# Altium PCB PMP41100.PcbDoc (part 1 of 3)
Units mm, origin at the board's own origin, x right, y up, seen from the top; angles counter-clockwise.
Board outline 49.66 x 37.36 mm, 2 copper layers (Top Layer, Bottom Layer), stack 1.016 mm thick; 100 components, 64 nets, 348 pads, 1132 vias.
Unrouted connection lines stored in the file: 60.
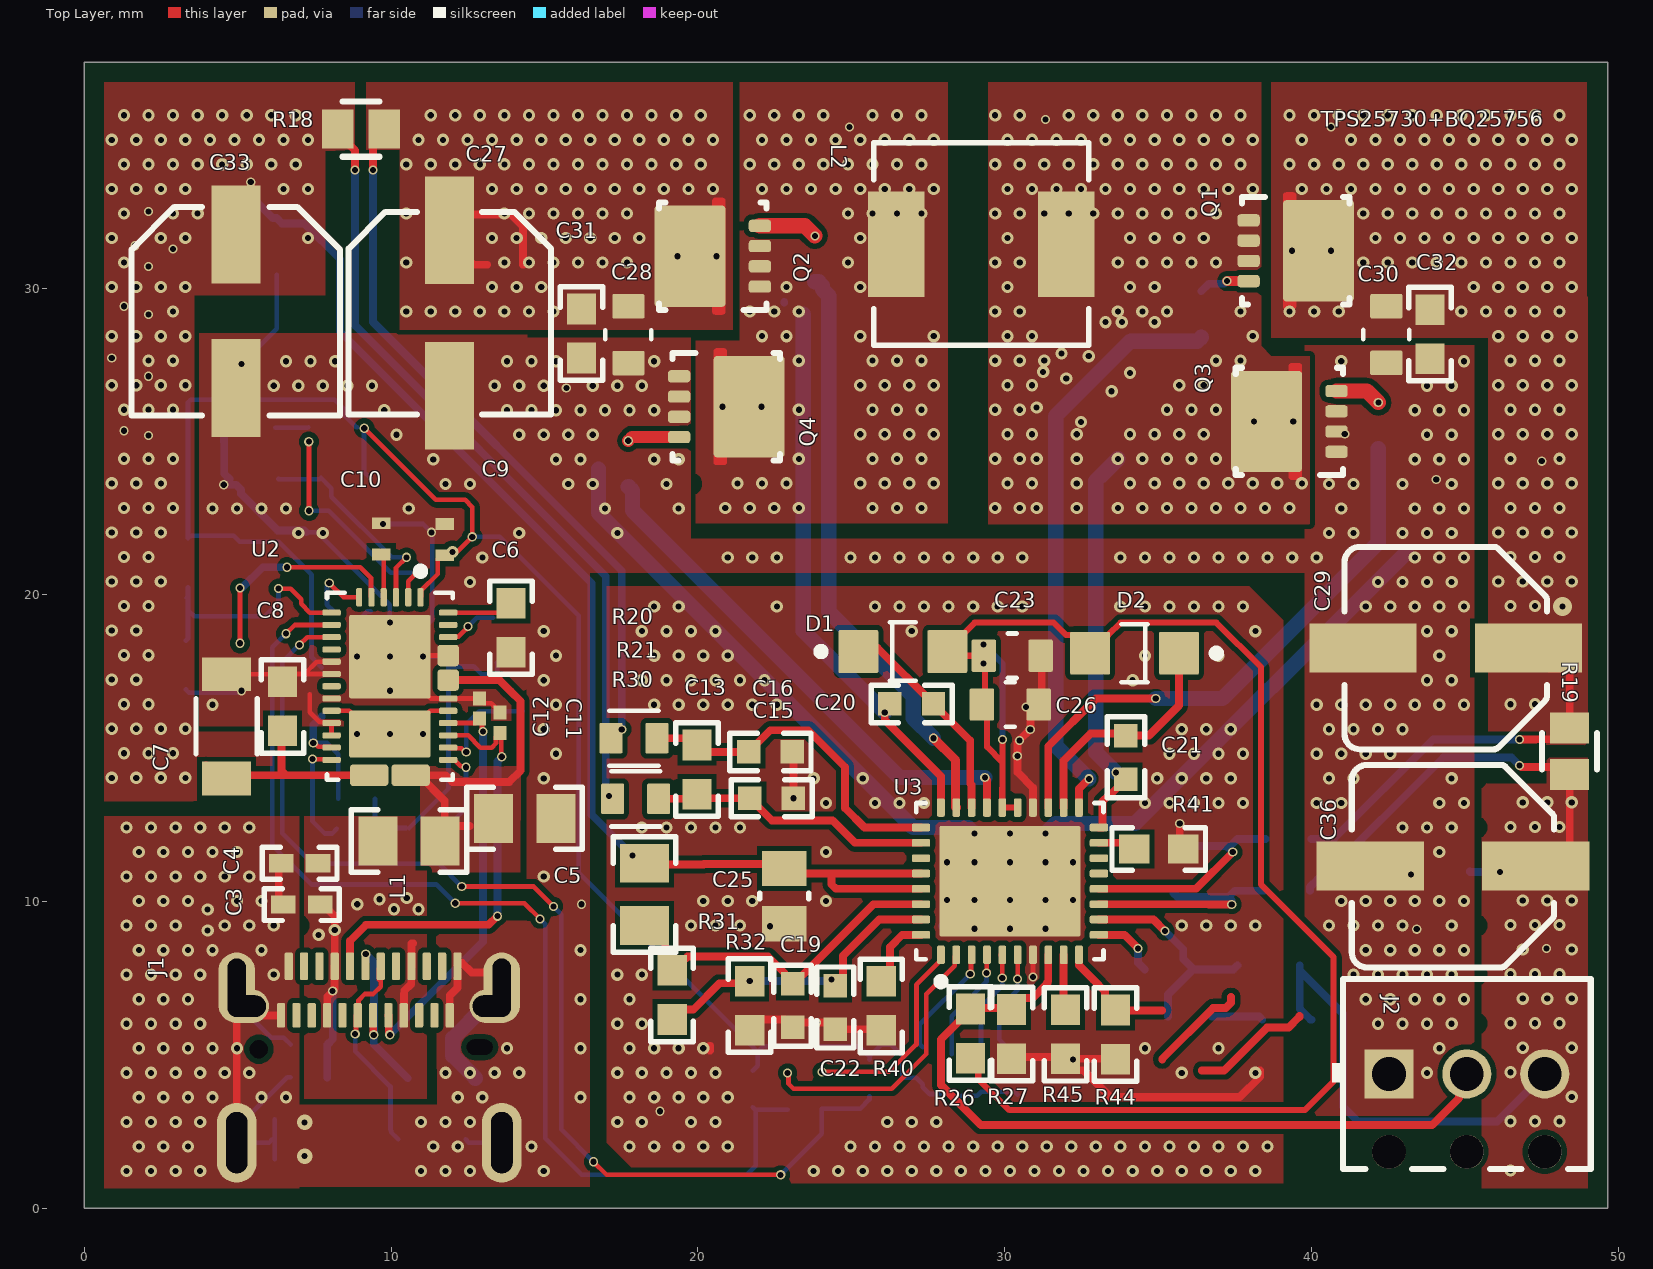
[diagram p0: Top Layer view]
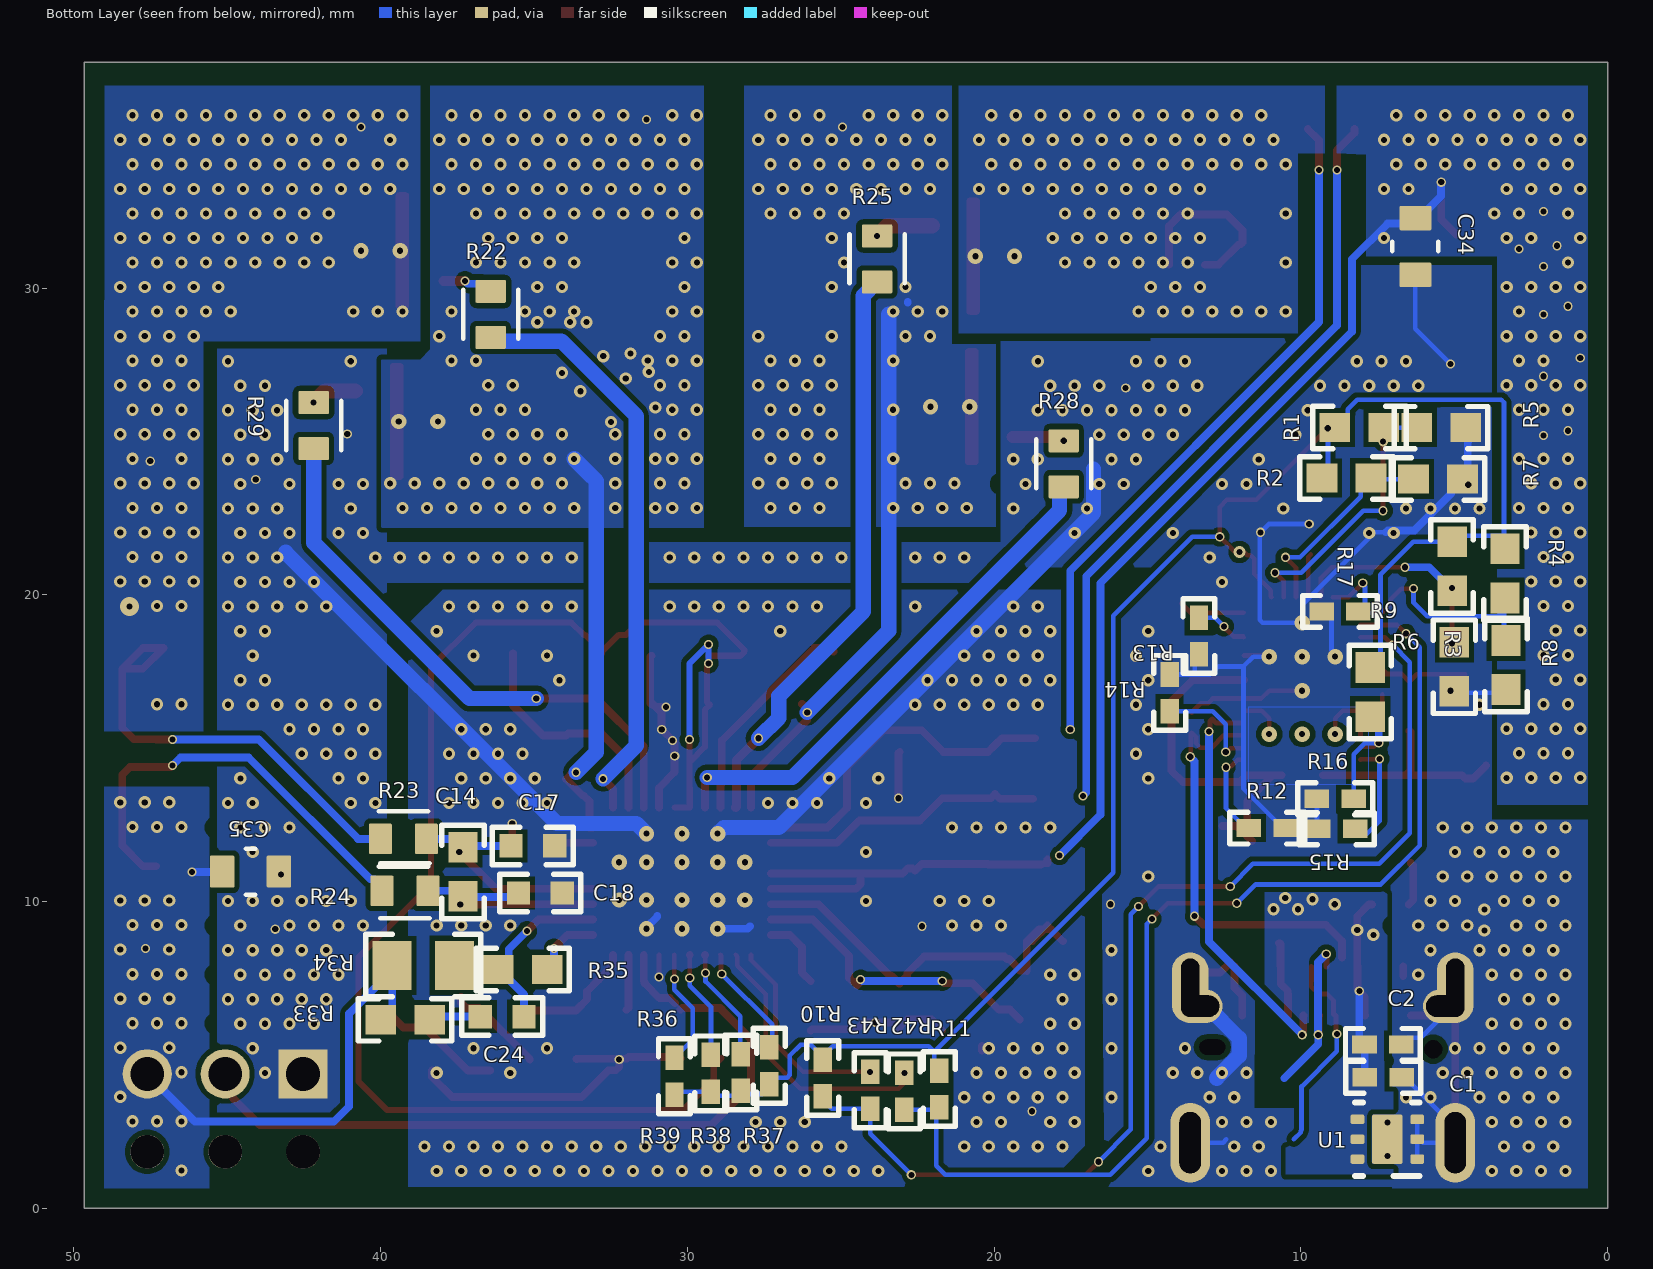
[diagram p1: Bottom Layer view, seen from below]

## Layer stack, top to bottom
Top Solder: solder mask 0.0102, Solder Resist, Dk 3.5
Top Layer: signal copper 0.0356
Dielectric1: core 0.9449, FR-4 High Tg, Dk 4.8
Bottom Layer: signal copper 0.0356
Bottom Solder: solder mask 0.0102, Solder Resist, Dk 3.5

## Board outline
0,0 0,37.358 49.657,37.358 49.657,0

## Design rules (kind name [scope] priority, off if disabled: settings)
AcuteAngle [All] p1: minimum=4.50000000000000E+0001 checktracksonly=FALSE
AssemblyTestPointUsage [All] p1: valid=2
BoardOutlineClearance BoardOutlineClearance_MountingHoles [OnCopper and InComponentClass('Mounting Holes')] p1: gap=1 ignorepadtopadclearanceinfootprint=FALSE
BoardOutlineClearance BoardOutlineClearance_Poly [OnCopper and IsPoly] p2: gap=0.635 ignorepadtopadclearanceinfootprint=FALSE
BoardOutlineClearance [OnCopper and Not InComponentClass('Logo') and not InComponentClass('FiducialMark') and not InRegion(1000,500,4000,800) and not InPoly] p3: gap=1.016 ignorepadtopadclearanceinfootprint=FALSE
Clearance "HV LV" [InNetClass('HV') vs InNetClass('LV')] p1: gap=0.17 ignorepadtopadclearanceinfootprint=TRUE
Clearance Clearance_Poly [InPolygon] p2: gap=0.17 ignorepadtopadclearanceinfootprint=TRUE
Clearance [All] p3: gap=0.17 ignorepadtopadclearanceinfootprint=TRUE
ComponentClearance ComponentClearance_MountingHoles_FiducialMarks [InComponentClass('Mounting Holes') vs InComponentClass('FiducialMark')] p1: gap=1.27 collisioncheckmode=3 verticalgap=0.254 showdistances=FALSE
ComponentClearance ComponentClearance_Shunt [InComponentClass('Header') vs InComponentClass('Shunt')] p2: gap=0.15 collisioncheckmode=3 verticalgap=0.15 showdistances=FALSE
ComponentClearance ComponentClearance_Logo [InComponentClass('Logo')] p3: gap=0.254 collisioncheckmode=3 verticalgap=0.254 showdistances=FALSE
ComponentClearance ComponentClearance_ScrewToNut [(HasFootprint('NY PMS 440 0025 PH')) vs (HasFootprint('Keystone_1902C'))] p4: gap=0.127 collisioncheckmode=3 verticalgap=0.254 showdistances=FALSE
ComponentClearance ComponentClearance_MountingHoles [InComponentClass('Mounting Holes')] p5: gap=0.254 collisioncheckmode=3 verticalgap=2540 showdistances=FALSE
ComponentClearance ComponentClearance_SmallPassives [HasFootprint('0201*') or HasFootprint('0402*') or HasFootprint('0508') or HasFootprint('0603*') or HasFootprint('0612') or HasFootprint('0805*') or HasFootprint('0815*') or HasFootprint('0830*') or HasFootprint('1206*') or HasFootprint('1210*') or HasFootprint('1808*') or HasFootprint('1812*') or HasFootprint('1825*') or HasFootprint('2010*') or HasFootprint('2220*') or HasFootprint('2225*') or HasFootprint('2512*') or HasFootprint('2728*') or HasFootprint('3518*') vs HasFootprint('0201*') or HasFootprint('0402*') or HasFootprint('0508') or HasFootprint('0603*') or HasFootprint('0612') or HasFootprint('0805*') or HasFootprint('0815*') or HasFootprint('0830*') or HasFootprint('1206*') or HasFootprint('1210*') or HasFootprint('1808*') or HasFootprint('1812*') or HasFootprint('1825*') or HasFootprint('2010*') or HasFootprint('2220*') or HasFootprint('2225*') or HasFootprint('2512*') or HasFootprint('2728*') or HasFootprint('3518*')] p6: gap=0.254 collisioncheckmode=3 verticalgap=0.254 showdistances=FALSE
ComponentClearance ComponentClearance_THtoSMT [IsThruComponent vs IsSMTComponent] p7: gap=0.254 collisioncheckmode=3 verticalgap=0.254 showdistances=FALSE
ComponentClearance ComponentClearance_THtoTH [IsThruComponent vs IsThruComponent] p8: gap=0.1 collisioncheckmode=3 verticalgap=0.1 showdistances=FALSE
ComponentClearance [All] p9: gap=0.254 collisioncheckmode=3 verticalgap=0.254 showdistances=FALSE
DiffPairsRouting [All] p1: maxlimit=2.54 minlimit=0.254 mostfreqgap=0.254 toplayer_minwidth=0.381 toplayer_maxwidth=0.381 toplayer_prefwidth=0.381 bottomlayer_minwidth=0.381 bottomlayer_maxwidth=0.381 bottomlayer_prefwidth=0.381 maxuncoupledlength=25.4
FabricationTestPointUsage TestPointUsage [All] p1: valid=2 allowmultiple=FALSE
FabricationTestpoint Testpoint [All] p1: side=3 testpointundercomponent=TRUE minsize=1.016 maxsize=2.54 preferedsize=1.524 minholesize=0 maxholesize=1.016 preferedholesize=0.813 testpointgrid=0.025 allowsidetop=TRUE allowsidebottom=TRUE usegrid=TRUE gridtolerance=0
FanoutControl Fanout_LCC [IsLCC] p1: bgadir=Out bgaviamode=Centered fanoutstyle=Auto fanoutdirection=Alternating viagrid=0.025 // Fanout_LCC (Default Rule)
FanoutControl Fanout_BGA [IsBGA] p2: bgadir=Out bgaviamode=Centered fanoutstyle=Auto fanoutdirection=Alternating viagrid=0.025 // Fanout_BGA (Default Rule)
FanoutControl Fanout_Default [All] p4: bgadir=Out bgaviamode=Centered fanoutstyle=Auto fanoutdirection=Alternating viagrid=0.025 // Fanout_Default (Default Rule)
FanoutControl Fanout_Small [(CompPinCount < 5)] p5: bgadir=Out bgaviamode=Centered fanoutstyle=Auto fanoutdirection=OutThenIn viagrid=0.025 // Fanout_Small (Default Rule)
HoleSize [All] p1: absolutevalues=TRUE maxlimit=6.375 minlimit=0.2 maxpercent=80.000 minpercent=20.000
MinimumAnnularRing MinimumAnnularRing_ThermalPadVias [IsVia and InAnyComponent] p1: minimumring=0.15
MinimumAnnularRing [All] p2: minimumring=0.2
MinimumSolderMaskSliver MinimumSolderMaskSliver_Logo [InComponentClass('Logo') vs InComponentClass('Logo')] p1: minsoldermaskwidth=0.018
MinimumSolderMaskSliver [All] p2: minsoldermaskwidth=0.1
PlaneConnect [All] p1: planeconnectstyle=Relief reliefexpansion=0.254 reliefentries=4 reliefconductorwidth=0.254 reliefairgap=0.254
PolygonConnect [All] p1: connectstyle=Direct reliefconductorwidth=0.254 reliefentries=4 polygonreliefangle="90 Angle" airgapwidth=0.254
RoutingVias ThermalPadVias [IsVia and InAnyComponent] p1: holewidth=0.2 width=0.5 viastyle="Through Hole" minholewidth=0.2 minwidth=0.5 maxholewidth=0.33 maxwidth=0.6
RoutingVias [All] p2: holewidth=0.406 width=0.864 viastyle="Through Hole" minholewidth=0.2 minwidth=0.61 maxholewidth=1.016 maxwidth=1.651
SilkToBoardRegionClearance [Not ((IsComment or IsDesignator) And (Hide <> 'False')) and not InRegion(1000,500,4000,800)] p1:
SilkToSilkClearance SilkToSilkClearance_Pb-FreeLogo [(HasFootprint('Pb-Free_Overlay_Medium') OR HasFootprint('Pb-Free_Overlay_Small')) vs (HasFootprint('Pb-Free_Overlay_Medium') OR HasFootprint('Pb-Free_Overlay_Small'))] p1: silktosilkclearance=0
SilkToSilkClearance [All] p2: silktosilkclearance=0.1
SilkToSolderMaskClearance SilkToComponentPadClearance [(IsPad or IsFill or IsRegion) and InAnycomponent] p1: minsilkscreentomaskgap=0.127 clearancetoexposedcopper=TRUE
SilkToSolderMaskClearance "Silk to Solder Mask Opening" [All] p2: minsilkscreentomaskgap=0.1 clearancetoexposedcopper=FALSE
SolderMaskExpansion [All] p1: expansion=0.05 istentingtop=FALSE
UnRoutedNet [All] p1: checkbadconnections=TRUE
Width [All] p1: maxlimit=2.54 minlimit=0.152 preferedwidth=0.254
14 further rules are at their usual default settings.

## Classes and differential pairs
net class HHV: BAT BTST2 HIDRV2 NetQ1_4 P_OUT SRN SRP SW2
net class LV: LODRV1 LODRV2 PGND
net class HV: ACN ACP ACUV BTST1 HIDRV1 NetQ2_4 SW1 VSYS
component class "PD Controller": C1 C2 C3 C4 C5 C6 C7 C8 C9 C10 C11 C12 J1 L1 R1 R2 R3 R4 R5 R6 R7 R8 R9 R10 R11 R12 R13 R14 R15 R16 R17 U1 U2
component class "Charger BQ25756": C13 C14 C15 C16 C17 C18 C19 C20 C21 C22 C23 C24 C25 C26 C27 C28 C29 C30 C31 C32 C33 C34 C35 C36 D1 D2 J2 L2 Q1 Q2 Q3 Q4 R18 R19 R20 R21 R22 R23 R24 R25 R26 R27 R28 R29 R30 R31 R32 R33 R34 R35 R36 R37 R38 R39 R40 R41 R42 R43 R44 R45 R48 R52 R60 U3
component class Logo: Logo1
component class Hardware: Logo1 Logo2 ZZ1 ZZ2 ZZ3 ZZ4
component class AssemblyNote: ZZ1 ZZ2 ZZ3 ZZ4

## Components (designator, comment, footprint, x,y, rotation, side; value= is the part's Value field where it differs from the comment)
C1 "C0402C103J5RACTU" 0402 7.316,4.27 r180 bottom value=0.01uF
C2 "C0402C103J5RACTU" 0402 7.324,5.341 r180 bottom value=0.01uF
C3 "C0402C103J5RACTU" 0402 7.082,9.904 r180 top value=0.01uF
C4 "C0402C103J5RACTU" 0402 7.015,11.254 r180 top value=0.01uF
C5 "GRM21BR61H475KE51L" 0805_HV 14.351,12.716 r0 top value=4.7uF
C6 "GCM188R71H104KA57D" 0603 13.904,18.929 r270 top value=0.1uF
C7 "CL31B106KBHNNNE" 1206_180 4.635,15.71 r90 top value=10uF
C8 "GCM188R71H104KA57D" 0603 6.46,16.365 r90 top value=0.1uF
C9 "CL05A106MP5NUNC" 0402_070 11.746,21.801 r270 top value=10uF
C10 "CL05A106MP5NUNC" 0402_070 9.676,21.824 r270 top value=10uF
C11 "CGA1A2X7R1H331K030BA" 0201_033 13.552,15.83 r90 top value=330pF
C12 "CGA1A2X7R1H331K030BA" 0201_033 12.885,16.294 r90 top value=330pF
C13 "C0603C474K4RACTU" 0603 19.97,14.305 r90 top value=0.47uF
C14 "C0603C474K4RACTU" 0603 37.319,10.971 r270 bottom value=0.47uF
C15 "HMK107B7104KAHT" 0603_HV 22.402,13.369 r0 top value=0.1uF
C16 "HMK107B7104KAHT" 0603_HV 22.367,14.881 r0 top value=0.1uF
C17 "HMK107B7104KAHT" 0603_HV 35.038,11.815 r180 bottom value=0.1uF
C18 "HMK107B7104KAHT" 0603_HV 34.795,10.282 r180 bottom value=0.1uF
C19 "HMK107B7104KAHT" 0603_HV 23.087,6.609 r270 top value=0.1uF
C20 "06033C104KAT2A" 0603_HV 26.97,16.446 r0 top value=0.1uF
C21 "06033C104KAT2A" 0603_HV 33.953,14.7 r270 top value=0.1uF
C22 "HMK107B7104KAHT" 0603_HV 24.479,6.547 r270 top value=0.1uF
C23 "CGA4J1X7R1E475K125AE" FP-CGA4J1X7R1E475K125AE_0805-MFG 30.247,18.016 r0 top value=4.7µF
C24 "GCM1885C2A101JA16D" 0603_HV 36.039,6.252 r180 bottom value=100pF
C25 "08051C105K4Z2A" 0805_150 22.816,10.182 r270 top value=1uF
C26 "CGA4J1X7R1E475K125AE" FP-CGA4J1X7R1E475K125AE_0805-MFG 30.184,16.424 r0 top value=4.7µF
C27 "EEHZA1V470P" SM_RADIAL_6.3AMM 11.902,29.187 r270 top value=47uF
C28 "C2012X7R1H475K125AC" FP-C2012X7R1H475K125AC_0805-MFG 17.735,28.483 r90 top
C29 "UCM1H470MCL1GS" CM_630x580 44.381,18.264 r180 top value=47uF
C30 "C2012X7R1H475K125AC" FP-C2012X7R1H475K125AC_0805-MFG 42.444,28.487 r90 top
C31 "C0603C104K5RACTU" 0603 16.201,28.52 r270 top value=0.1uF
C32 "C0603C104K5RACTU" 0603 43.865,28.499 r270 top value=0.1uF
C33 "EEH-ZC1V680XP" ZC_D8 4.936,29.249 r270 top value=68uF
C34 "C2012X7R1H475K125AC" FP-C2012X7R1H475K125AC_0805-MFG 6.265,31.36 r270 bottom
C35 "C2012X7R1H475K125AC" FP-C2012X7R1H475K125AC_0805-MFG 44.241,10.978 r0 bottom
C36 "UCM1H470MCL1GS" CM_630x580 44.615,11.155 r180 top value=47uF
D1 "V1FM10-M3/H" FP-V1FM10-M3-H_DO-219AB-MFG 26.682,18.151 r180 top
D2 "V1FM10-M3/H" FP-V1FM10-M3-H_DO-219AB-MFG 34.235,18.097 r0 top
J1 "DX07S024JJ2R1300" JAE_DX07S024JJ2R1300 9.286,0.34 r0 top
J2 "1725669" Phoenix_1725669 45.068,4.382 r0 top
L1 "FBMJ2125HM210NT" 0805_HV 10.58,11.974 r0 top value="21 ohm"
L2 "PCMB065T-8R2MS" IHLP-2525CZ 29.238,31.434 r0 top value=8.2uH
Logo1 "Texas Instruments" TI_Stacked_Overlay_Small 70.891,1.847 r0 top
Logo2 "FCC disclaimer" FCC_disclaimer 34.348,50.013 r0 top
Q1 "SiSS50DN" PowerPAK_1212-8 39.488,31.218 r0 top value=60V
Q2 "SiSS50DN" PowerPAK_1212-8 20.487,31.04 r180 top value=60V
Q3 "SiSS50DN" PowerPAK_1212-8 39.284,25.654 r180 top value=60V
Q4 "SiSS50DN" PowerPAK_1212-8 20.924,26.135 r0 top value=60V
R1 "RT0603BRD07198KL" 0603 8.093,25.462 r0 bottom value=198k
R2 "RG1608P-222-B-T5" 0603 8.512,23.815 r0 bottom value=2.20k
R3 "RT0603BRD07162KL" 0603 5.066,20.93 r90 bottom value=162k
R4 "RT0603DRE07191KL" 0603 3.341,20.7 r90 bottom value=191k
R5 "RG1608P-222-B-T5" 0603 5.424,25.451 r0 bottom value=2.20k
R6 "RT0603DRE0737K9L" 0603 4.997,17.656 r90 bottom value=37.9k
R7 "RT0603BRD07198KL" 0603 5.53,23.777 r0 bottom value=198k
R8 "RT0603BRD079K42L" 0603 3.311,17.713 r90 bottom value=9.42k
R9 "RT0603BRD071KL" 0603 7.736,16.831 r90 bottom value=1.00k
R10 "CRCW04023K30JNED" 0402 25.593,4.251 r270 bottom value=3.3k
R11 "CRCW04023K30JNED" 0402 21.788,3.891 r270 bottom value=3.3k
R12 "ERJ-2RKF1002X" 0402 11.093,12.399 r0 bottom value=10.0k
R13 "ERJ-2RKF1002X" 0402 13.321,18.658 r90 bottom value=10.0k
R14 "ERJ-2RKF1002X" 0402 14.279,16.803 r270 bottom value=10.0k
R15 "ERJ-2RKF1002X" 0402 8.831,12.376 r180 bottom value=10.0k
R16 "ERJ-2RKF1002X" 0402 8.876,13.352 r180 bottom value=10.0k
R17 "ERJ-2RKF1002X" 0402 8.724,19.459 r180 bottom value=10.0k
R18 "WSLP08055L000FEA" WSL0805 9.014,35.185 r0 top value=0.005
R19 "WSLP08055L000FEA" WSL0805 48.417,14.902 r270 top value=0.005
R20 "CRCW060310R0FKEB" FP-CRCW060310R0FKEB_0603-MFG 17.971,13.35 r180 top value=10
R21 "CRCW060310R0FKEB" FP-CRCW060310R0FKEB_0603-MFG 17.916,15.327 r180 top value=10
R22 "CRCW06030000Z0EA" FP-CRCW06031R50FKEAHP_0603-MFG 36.413,29.145 r270 bottom value=0
R23 "CRCW060310R0FKEB" FP-CRCW060310R0FKEB_0603-MFG 39.257,12.044 r180 bottom value=10
R24 "CRCW060310R0FKEB" FP-CRCW060310R0FKEB_0603-MFG 39.207,10.352 r180 bottom value=10
R25 "CRCW06030000Z0EA" FP-CRCW06031R50FKEAHP_0603-MFG 23.815,30.954 r270 bottom value=0
R26 "RC0603FR-075K23L" 0603 28.888,5.698 r270 top value=5.23k
R27 "RC0603FR-0730K1L" 0603 30.225,5.68 r90 top value=30.1k
R28 "CRCW06030000Z0EA" FP-CRCW06031R50FKEAHP_0603-MFG 17.728,24.273 r90 bottom value=0
R29 "CRCW06030000Z0EA" FP-CRCW06031R50FKEAHP_0603-MFG 42.183,25.521 r90 bottom value=0
R30 "CRCW08051M00FKEAC" 0805_HV 18.26,10.234 r90 top value=1.00Meg
R31 "RT0603DRE07383KL" 0603 19.162,6.958 r90 top value=383k
R32 "RT0603DRE0769K8L" 0603 21.689,6.609 r90 top value=69.8k
R33 "CRCW06031R10JNEA" 0603 39.201,6.147 r0 bottom value=1.1
R34 "ERJ-PB6B2493V" 0805_HV 38.609,7.92 r0 bottom value=249k
R35 "RT0603BRD0712K7L" 0603 35.368,7.785 r0 bottom value=12.7k
R36 "RC0402FR-0710K5L" 0402 30.42,4.304 r270 bottom value=10.5k
R37 "RC0402FR-0710K5L" 0402 27.331,4.65 r270 bottom value=10.5k
R38 "RC0402FR-0710K5L" 0402 28.264,4.428 r270 bottom value=10.5k
R39 "RC0402FR-0710K5L" 0402 29.232,4.4 r270 bottom value=10.5k
R40 "RC0603FR-07100KL" 0603 25.978,6.6 r90 top value=100k
R41 "CRCW06033K01FKEA" 0603 35.025,11.712 r180 top value=3.01k
R42 "CRCW04022R20JNED" 0402 22.926,3.813 r90 bottom value=2.2
R43 "CRCW04022R20JNED" 0402 24.043,3.848 r90 bottom value=2.2
R44 "RT0603BRD076K65L" 0603 33.616,5.665 r90 top value=6.65k
R45 "RG1608P-5622-B-T5" 0603 31.984,5.675 r90 top value=56.2k
U1 "TVS2200DRVR" DRV0006A 7.179,2.253 r0 bottom
U2 "TPS25730DRJKR" RJK0038B-MFG 9.957,17.021 r0 top
U3 "BQ25756RRVT" RRV0036A-MFG 30.174,10.666 r90 top
ZZ1 "This Assembly Note is for PCB labels only" AssemblyNoteLabel -19.881,65.964 r0 top
ZZ2 "These assemblies are ESD sensitive, ESD precautions shall be observed." AssemblyNote -19.881,63.198 r0 top
ZZ3 "These assemblies must be clean and free from flux and all contaminants. Use of no clean flux is not acceptable." AssemblyNote -19.881,60.949 r0 top
ZZ4 "These assemblies must comply with workmanship standards IPC-A-610 Class 2, unless otherwise specified." AssemblyNote -19.881,58.699 r0 top

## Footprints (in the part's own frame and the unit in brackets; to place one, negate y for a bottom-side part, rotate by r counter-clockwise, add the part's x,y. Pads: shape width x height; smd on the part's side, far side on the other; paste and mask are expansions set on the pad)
0201_033 [mm] "SMD, 2-Leads, Height 0.33mm"
  rect 0.46x0.42 smd mask+0.048: 1(-0.33,0) 2(0.33,0)
  body extent -0.31,-0.16 0.31,0.16, height 0.33
0402 [mm] "0402 from SM-752 data"
  rect 0.8x0.6 smd: 1(-0.6,0) 2(0.6,0)
  silkscreen extent -1.22,-0.52 1.22,0.52, body extent -0.55,-0.3 0.55,0.3, height 0.6
0402_070 [mil] "SMD, 2-Leads, Body 1.2x0.7mm, Height 0.7mm"
  rect 15x24 smd: 1(-20,0) 2(20,0)
  body extent -24,-14 24,14, height 28
0603 [mm] "0603 from SM-752 data"
  rect 1x0.95 smd: 1(-0.8,0) 2(0.8,0)
  silkscreen extent -1.52,-0.69 1.52,0.69, body extent -0.87,-0.47 0.87,0.47, height 1
0603_HV [mil] "Ernesto recommended land pattern.  26 mil between pads."
  rect 30x30 smd: 1(-28,0) 2(28,0)
  silkscreen extent -52,-24 52,24, body extent -34,-19 34,19, height 39
0805_150 [mm] "0805 / 1.5 mm height"
  rect 1.15x1.45 smd: 1(-0.9,0) 2(0.9,0)
  silkscreen extent -0.1,-0.8 0.1,0.8, body extent -1.1,-0.72 1.1,0.72, height 1.5
0805_HV [mil] "0805 with 30mil clearance between pads"
  rect 50x63 smd: 1(-40,0) 2(40,0)
  silkscreen extent -74,-40 74,40, body extent -43,-29 43,29, height 57
1206_180 [mm] "1206_180"
  rect 1.1x1.6 smd: 1(-1.7,0) 2(1.7,0)
  silkscreen extent -0.9,-1 0.9,1, body extent -1.75,-0.95 1.75,0.95, height 1.8
AssemblyNote [mm] "Assembly Note"
AssemblyNoteLabel [mm] "Assembly Note for PCB Labels"
CM_630x580 [mm] "SMD, 2-Leads, Dia 6.3mm"
  rect 3.5x1.6 smd: 1(-2.7,0) 2(2.7,0)
  silkscreen extent -3.3,-3.3 3.3,3.3, body extent -3.5,-3.3 3.5,3.3, height 6.1
DRV0006A [mm] "SON, 6-Leads, Body 2x2mm, Pitch 0.65mm, Thermal Pad 1.6x1mm, TI Recommended"
  rrect33% 0.45x0.3 smd: 1(-0.975,0.65) 2(-0.975,0) 3(-0.975,-0.65) 4(0.975,-0.65) 5(0.975,0) 6(0.975,0.65)
  rrect14% 1x0.7 on Bottom Paste: 7(0,-0.45) 7(0,0.45)
  rrect10% 1x1.6 smd paste-0.5: 7(0,0)
  silkscreen extent -1.05,-1.2 1.05,1.2, body extent -1.05,-1.05 1.05,1.05, height 0.81
FCC_disclaimer [mm]
FP-C2012X7R1H475K125AC_0805-MFG [mm]
  rrect13% 0.8x1.05 smd paste+0 mask+0: 1(-0.925,0) 2(0.925,0)
  silkscreen extent -0.15,-0.75 0.15,0.75, body extent -1.43,-0.85 1.43,0.85, height 0.25
FP-CGA4J1X7R1E475K125AE_0805-MFG [mm]
  rrect13% 0.8x1.05 smd paste+0 mask+0: 1(-0.925,0) 2(0.925,0)
  silkscreen extent -0.15,-0.72 0.15,0.72, body extent -1,-0.63 1,0.63, height 1.45
FP-CRCW06031R50FKEAHP_0603-MFG [mm]
  rrect13% 0.75x1 smd paste+0 mask+0: 1(-0.75,0) 2(0.75,0)
  silkscreen extent -0.8,-0.9 0.8,0.9, body extent -0.8,-0.43 0.8,0.43, height 0.55
FP-CRCW060310R0FKEB_0603-MFG [mm]
  rrect13% 0.75x1 smd paste+0 mask+0: 1(-0.75,0) 2(0.75,0)
  silkscreen extent -0.8,-0.9 0.8,0.9, body extent -0.77,-0.43 0.77,0.43, height 0.5
FP-V1FM10-M3-H_DO-219AB-MFG [mm]
  rrect8% 1.3x1.4 smd paste+0 mask+0: 1(1.45,0) 2(-1.45,0)
  silkscreen extent -0.43,-0.95 2.79,0.95, body extent -2.2,-1.05 2.2,1.05, height 0.25
IHLP-2525CZ [mm] "Vishay Dale recommended land pattern.  Document 34190 rev 10-Aug-06"
  rect 1.83x3.43 smd: 1(-2.77,0) 2(2.77,0)
  silkscreen extent -3.5,-3.3 3.5,3.3, body extent -3.62,-3.36 3.62,3.36, height 3
JAE_DX07S024JJ2R1300 [mm] "Receptacle, USB 3.1 Type C, R/A, SMT"
  rrect37% 0.27x0.9 smd: A1(-2.625,7.55) A2(-2.125,7.55) A3(-1.625,7.55) A4(-1.125,7.55) A5(-0.625,7.55) A6(-0.125,7.55) A7(0.375,7.55) A8(0.875,7.55) A9(1.375,7.55) A10(1.875,7.55) A11(2.375,7.55) A12(2.875,7.55)
  round 0.3 hole 0.6 unplated mask+0.102: ALIGN1(-3.6,4.85)
  rrect100% 0.55x0.3 hole 0.5 slot 0.85 at 0 deg unplated mask+0.102: ALIGN2(3.6,4.915)
  rrect37% 0.27x0.8 smd: B1(2.625,5.95) B2(2.125,5.95) B3(1.625,5.95) B4(1.125,5.95) B5(0.625,5.95) B6(0.125,5.95) B7(-0.375,5.95) B8(-0.875,5.95) B9(-1.375,5.95) B10(-1.875,5.95) B11(-2.375,5.95) B12(-2.875,5.95)
  rrect100% 1.2x2.3 hole 0.6 slot 1.9 at 90 deg: S1(-4.32,6.85) S2(4.32,6.85)
  rrect100% 1.45x1.1 hole 0.7 slot 1.25 at 0 deg: S1(-3.995,6.25) S2(3.995,6.25)
  rrect100% 1.3x2.6 hole 0.7 slot 2 at 90 deg: S3(-4.32,1.8) S4(4.32,1.8)
  body extent -4.47,-0.5 4.47,7.67, height 3.14
Phoenix_1725669 [mm] "Terminal Block, 3x1, 2.54 mm, TH"
  rect 1.6x1.6 hole 1.1: 1(-2.54,0)
  round 1.6 hole 1.1: 2(0,0) 3(2.54,0)
  round 1.1 hole 1.1 unplated mask+0: 4(-2.54,-2.54) 5(0,-2.54) 6(2.54,-2.54)
  silkscreen extent -4.4,-3.1 4.04,3.1, body extent -4.04,-3.1 4.04,3.1, height 8.5
PowerPAK_1212-8 [mm] "Vishay PowerPAK 1212-8, Body 3.4x3.2mm (max), Pitch 0.65mm, IPC Medium Density"
  rrect50% 0.73x0.4 smd paste-0.05 mask-0.05: 1(-1.535,0.991) 2(-1.535,0.33) 3(-1.535,-0.33) 4(-1.535,-0.991)
  rrect50% 0.71x0.4 smd paste-0.05 mask-0.05: 5(1.545,-0.991) 6(1.545,-0.33) 7(1.545,0.33) 8(1.545,0.991)
  rrect30% 0.33x0.6 on Top Paste: 9(-0.195,-1.55) 9(-0.195,1.55)
  rrect30% 0.33x3.7 on Top Solder: 9(-0.195,0)
  rrect11% 1.3x0.94 on Top Paste: 9(0.39,-0.57) 9(0.39,0.57)
  rrect6% 1.6x2.28 on Top Solder: 9(0.54,0)
  rrect9% 2.31x3.3 smd paste-2 mask-2: 9(0.745,0)
  Top Layer region: -0.41,-1.8 -0.41,1.8 -0.402,1.838 -0.381,1.871 -0.348,1.892 -0.31,1.9 -0.31,1.9 -0.08,1.9 -0.042,1.892 -0.009,1.871 0.012,1.838 0.02,1.8 0.02,1.8 0.02,-1.8 0.012,-1.838 -0.009,-1.871 -0.042,-1.892 -0.08,-1.9 -0.08,-1.9 -0.31,-1.9 -0.348,-1.892 -0.381,-1.871 -0.402,-1.838 -0.41,-1.8
  silkscreen extent -1.75,-1.75 1.75,1.75, body extent -1.65,-1.66 1.65,1.64, height 1.08
RJK0038B-MFG [mm]
  rrect50% 0.2x0.6 smd paste+0 mask-1000: 1(1,2.9) 2(0.6,2.9) 3(0.2,2.9) 4(-0.2,2.9) 5(-0.6,2.9) 6(-1,2.9)
  rrect50% 0.6x0.2 smd paste+0 mask-1000: 7(-1.9,2.4) 8(-1.9,2) 9(-1.9,1.6) 10(-1.9,1.2) 11(-1.9,0.8) 12(-1.9,0.4) 13(-1.9,0) 14(-1.9,-0.4) 15(-1.9,-0.8) 16(-1.9,-1.2) 17(-1.9,-1.6) 18(-1.9,-2) 19(-1.9,-2.4) 26(1.9,-2.4) 27(1.9,-2) 28(1.9,-1.6) 29(1.9,-1.2) 30(1.9,-0.8) 31(1.9,-0.4) 36(1.9,1.6) 37(1.9,2) 38(1.9,2.4)
  rrect29% 1.253x0.7 smd paste-1000 mask-1000: 20-21-22(-0.677,-2.9) 23-24-25(0.677,-2.9)
  rrect29% 0.7x0.7 smd paste-1000 mask-1000: 32-33(1.9,0.2) 34-35(1.9,1)
  rrect4% 2.65x2.72 smd paste-1000 mask-1000: 39(0,0.965)
  rrect7% 2.65x1.53 smd paste-1000 mask-1000: 40(0,-1.56)
  silkscreen extent -2.05,-3.05 2.05,3.87, body extent -2.3,-3.35 2.35,3.3, height 0.25
RRV0036A-MFG [mm]
  rrect40% 0.6x0.25 smd paste+0 mask+0: 1(-2.4,2.25) 2(-2.4,1.75) 3(-2.4,1.25) 4(-2.4,0.75) 5(-2.4,0.25) 6(-2.4,-0.25) 7(-2.4,-0.75) 8(-2.4,-1.25) 9(-2.4,-1.75) 10(-2.4,-2.25) 19(2.4,-2.25) 20(2.4,-1.75) 21(2.4,-1.25) 22(2.4,-0.75) 23(2.4,-0.25) 24(2.4,0.25) 25(2.4,0.75) 26(2.4,1.25) 27(2.4,1.75) 28(2.4,2.25)
  rrect40% 0.25x0.6 smd paste+0 mask+0: 11(-1.75,-2.9) 12(-1.25,-2.9) 13(-0.75,-2.9) 14(-0.25,-2.9) 15(0.25,-2.9) 16(0.75,-2.9) 17(1.25,-2.9) 18(1.75,-2.9) 29(1.75,2.9) 30(1.25,2.9) 31(0.75,2.9) 32(0.25,2.9) 33(-0.25,2.9) 34(-0.75,2.9) 35(-1.25,2.9) 36(-1.75,2.9)
  rrect3% 3.6x4.6 smd paste-1000 mask+0: 37(0,0)
  silkscreen extent -3.4,-3.05 2.55,3.05, body extent -2.8,-3.3 2.8,3.3, height 0.25
SM_RADIAL_6.3AMM [mm] "Nichicon 6.3x5.8"
  rect 3.5x1.6 smd: 1(-2.7,0) 2(2.7,0)
  silkscreen extent -3.3,-3.29 3.3,3.31, body extent -3.5,-3.3 3.5,3.3, height 6.11
TI_Stacked_Overlay_Small [mm]
  silkscreen extent -10.63,-2.49 10.63,2.49
WSL0805 [mm] "Vishay"
  rect 1.02x1.27 smd: 1(-0.76,0) 2(0.76,0)
  silkscreen extent -0.6,-0.9 0.6,0.9, body extent -1.14,-0.76 1.14,0.76, height 0.59
ZC_D8 [mm] "SMD, 2-Leads, Dia 6.3mm"
  rect 3.2x1.6 smd: 1(-2.5,0) 2(2.5,0)
  silkscreen extent -3.4,-3.4 3.4,3.4, body extent -3.4,-3.4 3.4,3.4, height 8.01

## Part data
C1 C2 C3 C4: library part CMP-0006236-2, "CAP, CERM, 0.01 uF, 50 V, +/- 5%, X7R, 0402", Cap_Case=0402, Manufacturer=Kemet, Supplier Part Number 1=399-7758-1-ND, TempCo=X7R, Tolerance_%=5%, Value1=Unknown, Value2=50V, ValueDisplayed=0.01uF
C5: library part CMP-0008309-2, "CAP, CERM, 4.7 uF, 50 V, +/- 10%, X5R, 0805", Cap_Case=0805, Manufacturer=MuRata, Supplier Part Number 1=GRM21BR61H475KE51L-ND, TempCo=X5R, Tolerance_%=10%, Value1=Unknown, Value2=50V, ValueDisplayed=4.7uF
C6 C8: library part CMP-0007144-4, "CAP, CERM, 0.1 uF, 50 V, +/- 10%, X7R, 0603", Cap_Case=0603, Manufacturer=MuRata, Supplier Part Number 1=490-4779-1-ND, TempCo=X7R, Tolerance_%=10%, Value1="0.02 ohm", Value2=50V, ValueDisplayed=0.1uF
C7: library part CMP-0008802-2, "CAP, CERM, 10 uF, 50 V, +/- 10%, X7R, 1206", Cap_Case=1206, Manufacturer=Samsung, Supplier Part Number 1=1276-6767-1-ND, TempCo=X7R, Tolerance_%=10%, Value1=Unknown, Value2=50V, ValueDisplayed=10uF
C9 C10: library part CMP-0006339-4, "CAP, CERM, 10 uF, 10 V, +/- 20%, X5R, 0402", Cap_Case=0402, Manufacturer="Samsung Electro-Mechanics", TempCo=X5R, Tolerance_%=20%, Value1=Unknown, Value2=10V, ValueDisplayed=10uF
C11 C12: library part CMP-0009653-3, "CAP, CERM, 330 pF, 50 V, +/- 10%, X7R, AEC-Q200 Grade 1, 0201", Cap_Case=0201_033, Manufacturer=TDK, Supplier Part Number 1=445-12111-1-ND, TempCo=X7R, Tolerance_%=10%, Value1="8.05302 ohm", Value2=50V, ValueDisplayed=330pF
C13 C14: library part CMP-0006944-4, "CAP, CERM, 0.47 uF, 16 V, +/- 10%, X7R, 0603", Cap_Case=0603, Manufacturer=Kemet, Supplier Part Number 1=399-4922-1-ND, TempCo=X7R, Tolerance_%=10%, Value1=Unknown, Value2=16V, ValueDisplayed=0.47uF
C15 C16 C17 C18 C19 C22: library part CMP-0081011-1, "CAP, CERM, 0.1 µF, 100 V,+/- 10%, X7R, AEC-Q200 Grade 1, 0603", Cap_Case=0603, Manufacturer="Taiyo Yuden", Supplier Part Number 1=587-6009-1-ND, TempCo=X7R, Tolerance_%=10%, Value2=100V, ValueDisplayed=0.1µF
C20 C21: library part CMP-0006753-4, "CAP, CERM, 0.1 uF, 25 V, +/- 10%, X7R, 0603", Cap_Case=0603, Manufacturer=AVX, Supplier Part Number 1=478-3714-1-ND, TempCo=X7R, Tolerance_%=10%, Value1="0.05 ohm", Value2=25V, ValueDisplayed=0.1uF
C23 C26: library part CMP-0093626-1, "Cap Ceramic 4.7uF 25V X7R 10% Pad SMD 0805 +125°C Automotive T/R", Manufacturer="TDK Corporation", Operating Temperature Range="-55°C to +125°C", TempCo=15%, Temperature Characteristic=X7R, Tolerance_%=0.1%, ValueDisplayed=4.7uF
C24: library part CMP-0007130-4, "CAP, CERM, 100 pF, 100 V, +/- 5%, C0G/NP0, AEC-Q200 Grade 1, 0603", Cap_Case=0603, Manufacturer=MuRata, Supplier Part Number 1=490-4771-1-ND, TempCo=C0G/NP0, Tolerance_%=5%, Value1=Unknown, Value2=100V, ValueDisplayed=100pF
C25: library part CMP-0861070-1, "CAP, CERM, 1 µF, 100 V,+/- 10%, X7R, AEC-Q200 Grade 1, 0805", Cap_Case=0805, Manufacturer=AVX, TempCo=X7R, Tolerance_%=10%, Value2=100V, ValueDisplayed=1µF
C27: library part CMP-0012588-1, "CAP, Polymer Hybrid, 47 uF, 35 V, +/- 20%, 60 ohm, 6.3x5.8 SMD", Manufacturer=Panasonic, Supplier Part Number 1=P15454CT-ND, Tolerance_%=20%, Value1="60 ohm", Value2=35V, ValueDisplayed=47uF
C28 C30 C34 C35: library part CMP-0088943-1, "4.7µF ±10% 50V Ceramic Capacitor X7R 0805 (2012 Metric)", Digikey Part Number=445-C2012X7R1H475K125ACCT-ND, Manufacturer=TDK, Mouser Part Number=810-C2012X7R475K125C, Operating Temperature Range="-55°C to +125°C", TempCo=15%, Temperature Characteristic=X7R, Tolerance_%=10%, ValueDisplayed=4.7uF
C29 C36: library part CMP-0011409-1, "CAP, AL, 47 uF, 50 V, +/- 20%, SMD", Cap_Case=6.3x5.8mm, Manufacturer=Nichicon, Supplier Part Number 1=493-14536-1-ND, Tolerance_%=20%, Value1=Unknown, Value2=50V, ValueDisplayed=47uF
C31 C32: library part CMP-0006861-3, "CAP, CERM, 0.1 uF, 50 V, +/- 10%, X7R, 0603", Cap_Case=0603, Manufacturer=Kemet, Supplier Part Number 1=399-5089-1-ND, TempCo=X7R, Tolerance_%=10%, Value1=Unknown, Value2=50V, ValueDisplayed=0.1uF
C33: library part CMP-0012262-1, "CAP, Aluminum Polymer, 68 uF, 35 V, +/- 20%, 0.035 ohm, AEC-Q200 Grade 1, D6.3xL7.7mm SMD", Cap_Case=6.3x7.7mm, Manufacturer=Panasonic, Supplier Part Number 1=P15474CT-ND, Tolerance_%=20%, Value1="0.035 ohm", Value2=35V, ValueDisplayed=68uF
D1 D2: library part CMP-0093639-2, "Diode Schottky 1A Surface Mount DO-219AB (SMF)", Digikey Part Number=112-V1FM10-M3/HCT-ND, Forward Current=1A, Manufacturer=Vishay, Max Surge Forward Current=30A, Mouser Part Number=78-V1FM10-M3/H, Operating Temperature Range="-40°C to +175°C", Peak Reverse Current=0.2uA, ValueDisplayed=95pF
J1: library part CMP-0085712-2, "Receptacle, USB 3.1 Type C, R/A, Gold, SMT", Color=Black, Current_A=1.25A, Manufacturer="JAE Electronics", Voltage_V=20V
J2: library part CMP-0055500-1, "Terminal Block, 3x1, 2.54 mm, TH", Manufacturer="Phoenix Contact", Supplier Part Number 1=277-1274-ND
L1: library part CMP-0003375-1, "Ferrite Bead, 21 ohm @ 100 MHz, 6 A, 0805", Manufacturer="Taiyo Yuden", Supplier Part Number 1=587-1765-1-ND, Value1="0.004 ohm", Value2=6A, ValueDisplayed="21 ohm"
L2: library part CMP-0098924-1, "Cyntech, 8.2uH, 5.3A, 45mOhm", DC Resistance=43mOhm, DC Resistance Max=45mOhm, Inductance=8.2uH, Manufacturer=Cyntech, Operating Temperature Max=125°C, Operating Temperature Min=-40°C, Performance Rated Current=4.35A, Saturation Current=12.2A, Self Resonant Frequency=15MHz
Logo1: library part CMP-0074838-1, "Texas Instrument Corporate Signature"
Logo2: library part CMP-0074847-1, "FCC_disclaimer"
Q1 Q2 Q3 Q4: library part CMP-0000866-2, "MOSFET, N-CH, 45 V, 4mR, PowerPAK 1212", Alternate Manufacturer=None, Manufacturer=Vishay-Siliconix, Value1=0.07, Value2="13 nC"
R1 R7: library part CMP-0023852-1, "RES, 198 k, 0.1%, 0.1 W, 0603", Manufacturer="Yageo America", Power_W=100mW, TempCo="25 ppm/C", Tolerance_%=0.1%, Value2=0.1W, Value_Code=198k
R2 R5: library part CMP-0023473-2, "RES, 2.20 k, 0.1%, 0.1 W, 0603", Manufacturer="Susumu Co Ltd", Power_W=100mW, Supplier Part Number 1=RG16P2.2KBCT-ND, TempCo="25 ppm/C", Tolerance_%=0.1%, Value2=0.1W, Value_Code=2k20, ValueDisplayed=2.20k
R3: library part CMP-0023788-2, "RES, 162 k, 0.1%, 0.1 W, 0603", Manufacturer="Yageo America", Power_W=100mW, TempCo="25 ppm/C", Tolerance_%=0.1%, Value2=0.1W, Value_Code=162k
R4: library part CMP-0024779-3, "RES, 191 k, 0.5%, 0.1 W, 0603", Manufacturer="Yageo America", Power_W=100mW, TempCo="50 ppm/C", Tolerance_%=0.5%, Value2=0.1W, Value_Code=191k
R6: library part CMP-0025190-2, "RES, 37.9 k, 0.5%, 0.1 W, 0603", Manufacturer="Yageo America", Power_W=100mW, TempCo="50 ppm/C", Tolerance_%=0.5%, Value2=0.1W, Value_Code=37k9, ValueDisplayed=37.9k
R8: library part CMP-0024554-2, "RES, 9.42 k, 0.1%, 0.1 W, 0603", Manufacturer="Yageo America", Power_W=100mW, TempCo="25 ppm/C", Tolerance_%=0.1%, Value2=0.1W, Value_Code=9k42, ValueDisplayed=9.42k
R9: library part CMP-0023919-1, "RES, 1.00 k, 0.1%, 0.1 W, 0603", Manufacturer="Yageo America", Power_W=100mW, Supplier Part Number 1=603-RT0603BRD071KL, TempCo="25 ppm/C", Tolerance_%=0.1%, Value2=0.1W, Value_Code=1k00, ValueDisplayed=1.00k
R10 R11: library part CMP-0026918-5, "RES, 3.3 k, 5%, 0.063 W, AEC-Q200 Grade 0, 0402", Manufacturer=Vishay-Dale, Power_W=63mW, Supplier Part Number 1=541-3.3KJCT-ND, TempCo="200 ppm/C", Tolerance_%=5%, Value2=0.063W, Value_Code=3k30, ValueDisplayed=3.3k
R12 R13 R14 R15 R16 R17: library part CMP-0026658-1, "RES, 10.0 k, 1%, 0.1 W, 0402", Manufacturer=Panasonic, Power_W=100mW, Supplier Part Number 1=P10.0KLCT-ND, TempCo="100 ppm/C", Tolerance_%=1%, Value2=0.1W, Value_Code=10k0, ValueDisplayed=10.0k
R18 R19: library part CMP-0021984-1, "RES, 0.005, 1%, 0.5 W, 0805", Manufacturer=Vishay-Dale, Power_W=500mW, TempCo="110 ppm/C", Tolerance_%=1%, Value2=0.5W, Value_Code=5L000, ValueDisplayed=0.005
R20 R21 R23 R24: library part CMP-0093685-1, "RES Thick Film, 10Ω, 1%, 0.1W, 100ppm/°C, 0603", Approved Alternate Part Number=541-1.00HHCT-ND, Manufacturer=Vishay, Operating Temperature Range="-55°C to +155°C", Power=100mW, TempCo=100ppm/°C, Tolerance_%=1%, Voltage=75V
R22 R25 R28 R29: library part CMP-0093629-1, "Thick Film Resistors - SMD 1/10watt ZEROohm Jumper", Manufacturer=Vishay, Operating Temperature Range="-55°C to +155°C", Power=250mW, Power_W=330mW, TempCo=100ppm/°C, Tolerance_%=1%
R26: library part CMP-0023199-5, "RES, 5.23 k, 1%, 0.1 W, 0603", Manufacturer=Yageo, Power_W=100mW, Supplier Part Number 1=311-5.23KHRCT-ND, TempCo="100 ppm/C", Tolerance_%=1%, Value2=0.1W, Value_Code=5k23, ValueDisplayed=5.23k
R27: library part CMP-0023018-5, "RES, 30.1 k, 1%, 0.1 W, 0603", Manufacturer=Yageo, Power_W=100mW, Supplier Part Number 1=311-30.1KHRCT-ND, TempCo="100 ppm/C", Tolerance_%=1%, Value2=0.1W, Value_Code=30k1, ValueDisplayed=30.1k
R30: library part CMP-0021522-3, "Thick Film Resistors - SMD 1/8Watt 1Mohms 1% Commercial Use", Manufacturer="Vishay / Dale", Power_W=125mW, Supplier Part Number 1=P1.00MCCT-ND, TempCo="100 ppm/C", Tolerance_%=1%, Value2=0.125W, Value_Code=1M00, ValueDisplayed=1.00M
R31: library part CMP-0025195-3, "RES, 383 k, 0.5%, 0.1 W, 0603", Manufacturer="Yageo America", Power_W=100mW, TempCo="50 ppm/C", Tolerance_%=0.5%, Value2=0.1W, Value_Code=383k
R32: library part CMP-0025509-3, "RES, 69.8 k, 0.5%, 0.1 W, 0603", Manufacturer="Yageo America", Power_W=100mW, TempCo="50 ppm/C", Tolerance_%=0.5%, Value2=0.1W, Value_Code=69k8, ValueDisplayed=69.8k
R33: library part CMP-0025744-3, "RES, 1.1, 5%, 0.1 W, 0603", Manufacturer=Vishay-Dale, Power_W=100mW, Supplier Part Number 1=541-1.1GCT-ND, TempCo="200 ppm/C", Tolerance_%=5%, Value2=0.1W, Value_Code=1R10, ValueDisplayed=1.1
R34: library part CMP-0018933-2, "Thick Film Resistors - SMD 0805 Anti-Surge Res. 0.1%, 249Kohm", Manufacturer=Panasonic, Power_W=125mW, Supplier Part Number 1=RG20P249KBCT-ND, TempCo="25 ppm/C", Tolerance_%=0.1%, Value2=0.125W, Value_Code=249k
R35: library part CMP-0023708-2, "RES, 12.7 k, 0.1%, 0.1 W, 0603", Manufacturer="Yageo America", Power_W=100mW, TempCo="25 ppm/C", Tolerance_%=0.1%, Value2=0.1W, Value_Code=12k7, ValueDisplayed=12.7k
R36 R37 R38 R39: library part CMP-0078781-1, "RES, 10.5 k, 1%, 0.063 W, 0402", Manufacturer="Yageo America", Power_W=63mW, Supplier Part Number 1=YAG2951CT-ND, TempCo="100 ppm/C", Tolerance_%=1%, Value2=0.063W, Value_Code=10k5, ValueDisplayed=10.5k
R40: library part CMP-0022735-5, "RES, 100 k, 1%, 0.1 W, 0603", Manufacturer=Yageo, Power_W=100mW, Supplier Part Number 1=311-100KHRCT-ND, TempCo="100 ppm/C", Tolerance_%=1%, Value2=0.1W, Value_Code=100k
R41: library part CMP-0022371-2, "RES, 3.01 k, 1%, 0.1 W, 0603", Manufacturer=Vishay-Dale, Power_W=100mW, Supplier Part Number 1=541-3.01KHCT-ND, TempCo="100 ppm/C", Tolerance_%=1%, Value2=0.1W, Value_Code=3k01, ValueDisplayed=3.01k
R42 R43: library part CMP-0026898-1, "RES, 2.2, 5%, 0.063 W, 0402", Manufacturer=Vishay-Dale, Power_W=63mW, Supplier Part Number 1=541-2.2JCT-ND, TempCo="200 ppm/C", Tolerance_%=5%, Value2=0.063W, Value_Code=2R20, ValueDisplayed=2.2
R44: library part CMP-0024438-1, "RES, 6.65 k, 0.1%, 0.1 W, 0603", Manufacturer="Yageo America", Power_W=100mW, TempCo="25 ppm/C", Tolerance_%=0.1%, Value2=0.1W, Value_Code=6k65, ValueDisplayed=6.65k
R45: library part CMP-0023575-1, "RES, 56.2 k, 0.1%, 0.1 W, 0603", Manufacturer="Susumu Co Ltd", Power_W=100mW, Supplier Part Number 1=RG16P56.2KBCT-ND, TempCo="25 ppm/C", Tolerance_%=0.1%, Value2=0.1W, Value_Code=56k2, ValueDisplayed=56.2k
U1: library part CMP-0077834-1, "22-V Precision Surge Protection Clamp, DRV0006A (WSON-6)", Alternate Manufacturer="Texas Instruments"
U2: library part CMP-0095900-3, "USB Type-C and USB PD Controller with Integrated Power Switches Optimized for Power Applications", Manufacturer="Texas Instruments", Operating Temperature Range=to
U3: library part CMP-0093460-1, Alternate Manufacturer=None, Manufacturer="Texas Instruments", Operating Temperature Range=to
ZZ1: library part CMP-0003616-3
ZZ2: library part CMP-0077236-1
ZZ3: library part CMP-0077237-1
ZZ4: library part CMP-0077238-1

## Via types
v1: diameter 0.4, hole 0.2, Top Layer to Bottom Layer, 988 vias
v2: diameter 0.3, hole 0.2, Top Layer to Bottom Layer, tented both sides, 103 vias
v3: diameter 0.5, hole 0.2, Top Layer to Bottom Layer, 34 vias
v4: diameter 0.4, hole 0.2, Top Layer to Bottom Layer, tented both sides, 5 vias
v5: diameter 0.4, hole 0.203, Top Layer to Bottom Layer, tented both sides, 1 vias
v6: diameter 0.61, hole 0.203, Top Layer to Bottom Layer, tented both sides, 1 vias

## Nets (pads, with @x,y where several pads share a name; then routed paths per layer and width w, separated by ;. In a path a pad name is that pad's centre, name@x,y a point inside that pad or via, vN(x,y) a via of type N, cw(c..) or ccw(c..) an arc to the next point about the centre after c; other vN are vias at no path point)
/INT: R37.1 U3.3 | length 3.8
  Top Layer w0.152: v2(28.88,7.638) 28.902,7.661 28.902,8.244 U3.3@28.924,8.266
  Bottom Layer w0.152: R37.1@27.331,5.25 27.238,5.343 27.238,5.996 v2(28.88,7.638)
/PG: R36.1 U3.6 | length 3.9
  Top Layer w0.152: v2(30.424,7.479) U3.6@30.424,8.266
  Bottom Layer w0.152: R36.1@30.42,4.904 29.82,5.504 29.82,6.52 30.424,7.124 v2(30.424,7.479)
